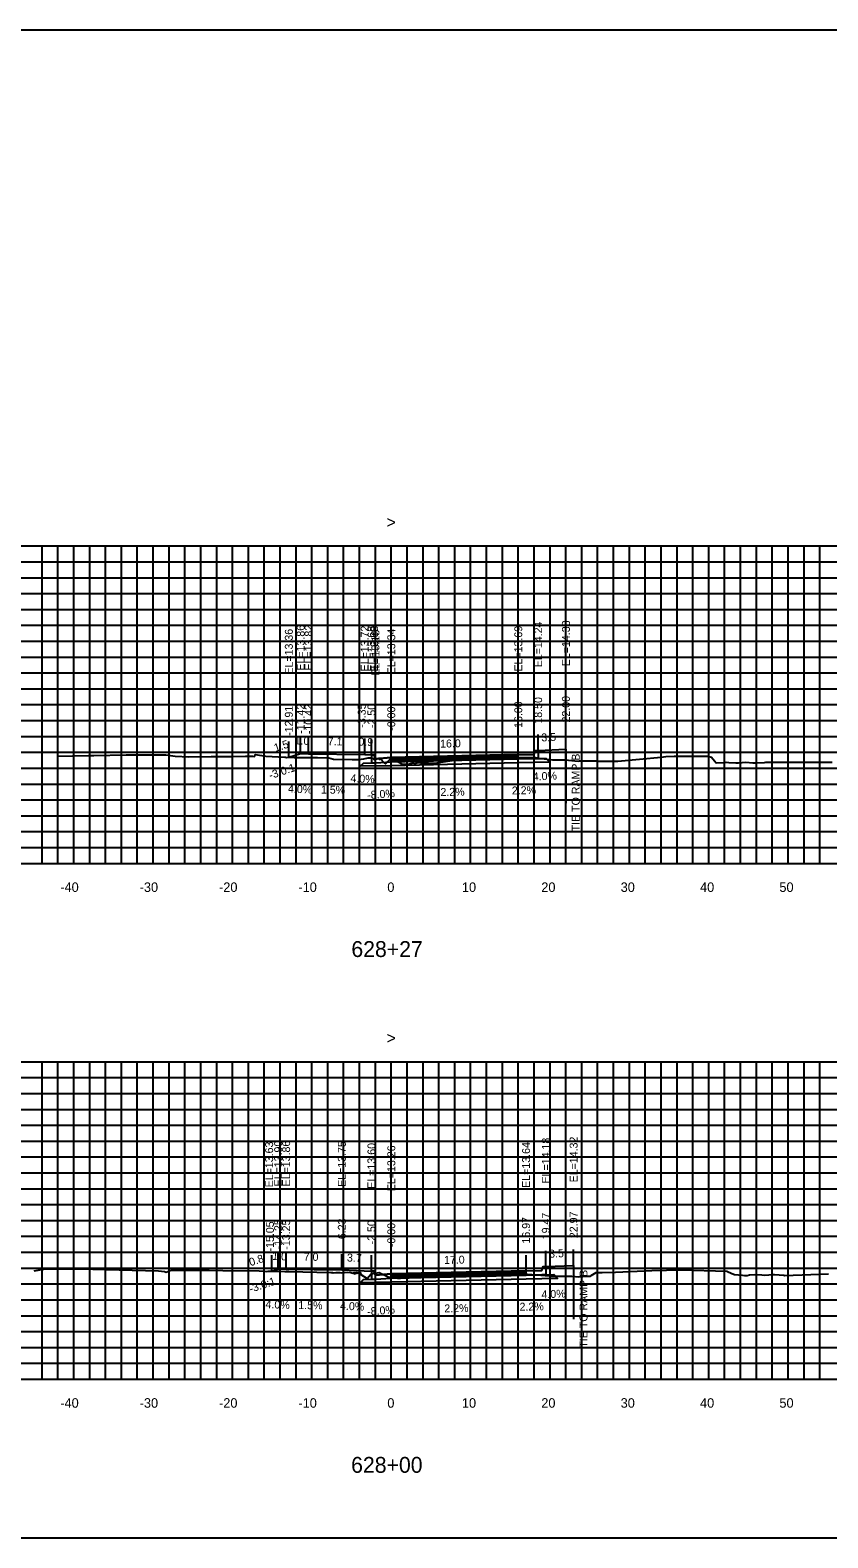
# Model space of a CAD drawing. Extents: x 1797645 to 1803805, y 248417 to 250269.
# Drawn here: x 1802585.5 to 1802686, y 250079.4 to 250269.4 of the extents above; entities that cross this region are included whole.
import ezdxf

# ---------------------------------------------------------------- set-up
doc = ezdxf.new("R2010")
doc.units = 0
for name, color, linetype in [('1', 7, 'Continuous'), ('10', 7, 'Continuous'), ('3', 7, 'Continuous'), ('4', 7, 'Continuous'), ('60', 7, 'Continuous'), ('BASE', 7, 'Continuous'), ('CL-CNST', 7, 'Continuous'), ('Level 62', 7, 'Continuous'), ('LOWER BINDER', 7, 'Continuous'), ('M-ROADS', 7, 'Continuous'), ('UPPER BINDER', 7, 'Continuous'), ('WEARING', 7, 'Continuous')]:
    doc.layers.add(name, color=color, linetype=linetype)

msp = doc.modelspace()

# ---------------------------------------------------------------- linework, layer by layer
for p, q in [((1802649.5, 250178.67), (1802649.5, 250180.67)), ((1802653, 250178.81), (1802653, 250180.81)), ((1802618.09, 250177.8), (1802618.09, 250179.8)), ((1802619.58, 250178.29), (1802619.58, 250180.29)), ((1802620.58, 250178.25), (1802620.58, 250180.25)), ((1802627.65, 250178.15), (1802627.65, 250180.15)), ((1802628.5, 250178.11), (1802628.5, 250180.11)), ((1802631, 250177.77), (1802631, 250179.77)), ((1802647, 250178.13), (1802647, 250180.13)), ((1802615.95, 250113.06), (1802615.95, 250115.06)), ((1802616.75, 250113.33), (1802616.75, 250115.33)), ((1802617.75, 250113.29), (1802617.75, 250115.29)), ((1802624.77, 250113.19), (1802624.77, 250115.19)), ((1802628.5, 250113.04), (1802628.5, 250115.04)), ((1802631, 250112.7), (1802631, 250114.7)), ((1802647.98, 250113.07), (1802647.98, 250115.07)), ((1802650.47, 250113.61), (1802650.47, 250115.61)), ((1802653.97, 250113.75), (1802653.97, 250115.75))]:
    msp.add_line(p, q)
for points in [[(1802481, 250079.43), (1802781, 250079.43), (1802781, 250269.43), (1802481, 250269.43)], [(1802631, 250177.77), (1802629, 250177.61), (1802628.83, 250178.11), (1802628.5, 250178.11), (1802628.5, 250177.08), (1802629, 250177.08), (1802631, 250177.24)], [(1802647, 250178.13), (1802649, 250178.17), (1802649.17, 250178.67), (1802649.5, 250178.67), (1802649.5, 250177.64), (1802649, 250177.64), (1802647, 250177.6)], [(1802631, 250112.7), (1802629, 250112.54), (1802628.83, 250113.04), (1802628.5, 250113.04), (1802628.5, 250112.01), (1802629, 250112.01), (1802631, 250112.17)], [(1802647.98, 250113.07), (1802649.98, 250113.11), (1802650.14, 250113.61), (1802650.47, 250113.61), (1802650.47, 250112.58), (1802649.98, 250112.58), (1802647.98, 250112.54)]]:
    msp.add_lwpolyline(points, close=True)
at = {"layer": '3'}
for p, q in [((1802653, 250178.81), (1802653, 250172.02)), ((1802653.97, 250113.75), (1802653.97, 250106.97))]:
    msp.add_line(p, q, dxfattribs=at)
at = {"layer": '60'}
for p, q in [((1802481, 250164.43), (1802781, 250164.43)), ((1802591, 250164.37), (1802591, 250164.43)), ((1802601, 250164.37), (1802601, 250164.43)), ((1802611, 250164.37), (1802611, 250164.43)), ((1802621, 250164.37), (1802621, 250164.43)), ((1802631, 250164.37), (1802631, 250164.43)), ((1802641, 250164.37), (1802641, 250164.43)), ((1802651, 250164.37), (1802651, 250164.43)), ((1802661, 250164.37), (1802661, 250164.43)), ((1802671, 250164.37), (1802671, 250164.43)), ((1802681, 250164.37), (1802681, 250164.43)), ((1802481, 250099.43), (1802781, 250099.43)), ((1802591, 250099.37), (1802591, 250099.43)), ((1802601, 250099.37), (1802601, 250099.43)), ((1802611, 250099.37), (1802611, 250099.43)), ((1802621, 250099.37), (1802621, 250099.43)), ((1802631, 250099.37), (1802631, 250099.43)), ((1802641, 250099.37), (1802641, 250099.43)), ((1802651, 250099.37), (1802651, 250099.43)), ((1802661, 250099.37), (1802661, 250099.43)), ((1802671, 250099.37), (1802671, 250099.43)), ((1802681, 250099.37), (1802681, 250099.43))]:
    msp.add_line(p, q, dxfattribs=at)
at = {"layer": 'BASE'}
for points in [[(1802631, 250177.24), (1802647, 250177.6), (1802649, 250177.64), (1802649.5, 250177.64), (1802650.5, 250177.66), (1802650.98, 250177.18), (1802647, 250177.1), (1802631, 250176.74), (1802627.09, 250176.66), (1802627.5, 250177.06), (1802628.5, 250177.08), (1802629, 250177.08)], [(1802631, 250112.17), (1802647.98, 250112.54), (1802649.98, 250112.58), (1802650.47, 250112.58), (1802651.47, 250112.61), (1802651.95, 250112.13), (1802647.98, 250112.04), (1802631, 250111.67), (1802627.09, 250111.58), (1802627.5, 250111.98), (1802628.5, 250112.01), (1802629, 250112.01)]]:
    msp.add_lwpolyline(points, close=True, dxfattribs=at)
at = {"layer": 'CL-CNST'}
for points in [[(1802618.09, 250177.8), (1802619.58, 250178.29), (1802620.58, 250178.25), (1802627.65, 250178.15), (1802628.5, 250178.11), (1802628.83, 250178.11), (1802629, 250177.61), (1802631, 250177.77), (1802647, 250178.13), (1802649, 250178.17), (1802649.17, 250178.67), (1802649.5, 250178.67), (1802653, 250178.81)], [(1802615.95, 250113.06), (1802616.75, 250113.33), (1802617.75, 250113.29), (1802624.77, 250113.19), (1802628.5, 250113.04), (1802628.83, 250113.04), (1802629, 250112.54), (1802631, 250112.7), (1802647.98, 250113.07), (1802649.98, 250113.11), (1802650.14, 250113.61), (1802650.47, 250113.61), (1802653.97, 250113.75)]]:
    msp.add_lwpolyline(points, dxfattribs=at)
at = {"layer": 'Level 62'}
for p, q in [((1802481, 250204.43), (1802781, 250204.43)), ((1802587, 250164.43), (1802587, 250204.43)), ((1802589, 250164.43), (1802589, 250204.43)), ((1802591, 250164.43), (1802591, 250204.43)), ((1802593, 250164.43), (1802593, 250204.43)), ((1802595, 250164.43), (1802595, 250204.43)), ((1802597, 250164.43), (1802597, 250204.43)), ((1802599, 250164.43), (1802599, 250204.43)), ((1802601, 250164.43), (1802601, 250204.43)), ((1802603, 250164.43), (1802603, 250204.43)), ((1802605, 250164.43), (1802605, 250204.43)), ((1802607, 250164.43), (1802607, 250204.43)), ((1802609, 250164.43), (1802609, 250204.43)), ((1802611, 250164.43), (1802611, 250204.43)), ((1802613, 250164.43), (1802613, 250204.43)), ((1802615, 250164.43), (1802615, 250204.43)), ((1802617, 250164.43), (1802617, 250204.43)), ((1802619, 250164.43), (1802619, 250204.43)), ((1802621, 250164.43), (1802621, 250204.43)), ((1802623, 250164.43), (1802623, 250204.43)), ((1802625, 250164.43), (1802625, 250204.43)), ((1802627, 250164.43), (1802627, 250204.43)), ((1802629, 250164.43), (1802629, 250204.43)), ((1802631, 250164.43), (1802631, 250204.43)), ((1802633, 250164.43), (1802633, 250204.43)), ((1802635, 250164.43), (1802635, 250204.43)), ((1802637, 250164.43), (1802637, 250204.43)), ((1802639, 250164.43), (1802639, 250204.43)), ((1802641, 250164.43), (1802641, 250204.43)), ((1802643, 250164.43), (1802643, 250204.43)), ((1802645, 250164.43), (1802645, 250204.43)), ((1802647, 250164.43), (1802647, 250204.43)), ((1802649, 250164.43), (1802649, 250204.43)), ((1802651, 250164.43), (1802651, 250204.43)), ((1802653, 250164.43), (1802653, 250204.43)), ((1802655, 250164.43), (1802655, 250204.43)), ((1802657, 250164.43), (1802657, 250204.43)), ((1802659, 250164.43), (1802659, 250204.43)), ((1802661, 250164.43), (1802661, 250204.43)), ((1802663, 250164.43), (1802663, 250204.43)), ((1802665, 250164.43), (1802665, 250204.43)), ((1802667, 250164.43), (1802667, 250204.43)), ((1802669, 250164.43), (1802669, 250204.43)), ((1802671, 250164.43), (1802671, 250204.43)), ((1802673, 250164.43), (1802673, 250204.43)), ((1802675, 250164.43), (1802675, 250204.43)), ((1802677, 250164.43), (1802677, 250204.43)), ((1802679, 250164.43), (1802679, 250204.43)), ((1802681, 250164.43), (1802681, 250204.43)), ((1802683, 250164.43), (1802683, 250204.43)), ((1802685, 250164.43), (1802685, 250204.43)), ((1802481, 250202.43), (1802781, 250202.43)), ((1802481, 250200.43), (1802781, 250200.43)), ((1802481, 250198.43), (1802781, 250198.43)), ((1802481, 250196.43), (1802781, 250196.43)), ((1802481, 250194.43), (1802781, 250194.43)), ((1802481, 250192.43), (1802781, 250192.43)), ((1802481, 250190.43), (1802781, 250190.43)), ((1802481, 250188.43), (1802781, 250188.43)), ((1802481, 250186.43), (1802781, 250186.43)), ((1802481, 250184.43), (1802781, 250184.43)), ((1802481, 250182.43), (1802781, 250182.43)), ((1802481, 250180.43), (1802781, 250180.43)), ((1802481, 250178.43), (1802781, 250178.43)), ((1802481, 250176.43), (1802781, 250176.43)), ((1802481, 250174.43), (1802781, 250174.43)), ((1802481, 250172.43), (1802781, 250172.43)), ((1802481, 250170.43), (1802781, 250170.43)), ((1802481, 250168.43), (1802781, 250168.43)), ((1802481, 250166.43), (1802781, 250166.43)), ((1802481, 250164.43), (1802781, 250164.43)), ((1802481, 250139.43), (1802781, 250139.43)), ((1802587, 250099.43), (1802587, 250139.43)), ((1802589, 250099.43), (1802589, 250139.43)), ((1802591, 250099.43), (1802591, 250139.43)), ((1802593, 250099.43), (1802593, 250139.43)), ((1802595, 250099.43), (1802595, 250139.43)), ((1802597, 250099.43), (1802597, 250139.43)), ((1802599, 250099.43), (1802599, 250139.43)), ((1802601, 250099.43), (1802601, 250139.43)), ((1802603, 250099.43), (1802603, 250139.43)), ((1802605, 250099.43), (1802605, 250139.43)), ((1802607, 250099.43), (1802607, 250139.43)), ((1802609, 250099.43), (1802609, 250139.43)), ((1802611, 250099.43), (1802611, 250139.43)), ((1802613, 250099.43), (1802613, 250139.43)), ((1802615, 250099.43), (1802615, 250139.43)), ((1802617, 250099.43), (1802617, 250139.43)), ((1802619, 250099.43), (1802619, 250139.43)), ((1802621, 250099.43), (1802621, 250139.43)), ((1802623, 250099.43), (1802623, 250139.43)), ((1802625, 250099.43), (1802625, 250139.43)), ((1802627, 250099.43), (1802627, 250139.43)), ((1802629, 250099.43), (1802629, 250139.43)), ((1802631, 250099.43), (1802631, 250139.43)), ((1802633, 250099.43), (1802633, 250139.43)), ((1802635, 250099.43), (1802635, 250139.43)), ((1802637, 250099.43), (1802637, 250139.43)), ((1802639, 250099.43), (1802639, 250139.43)), ((1802641, 250099.43), (1802641, 250139.43)), ((1802643, 250099.43), (1802643, 250139.43)), ((1802645, 250099.43), (1802645, 250139.43)), ((1802647, 250099.43), (1802647, 250139.43)), ((1802649, 250099.43), (1802649, 250139.43)), ((1802651, 250099.43), (1802651, 250139.43)), ((1802653, 250099.43), (1802653, 250139.43)), ((1802655, 250099.43), (1802655, 250139.43)), ((1802657, 250099.43), (1802657, 250139.43)), ((1802659, 250099.43), (1802659, 250139.43)), ((1802661, 250099.43), (1802661, 250139.43)), ((1802663, 250099.43), (1802663, 250139.43)), ((1802665, 250099.43), (1802665, 250139.43)), ((1802667, 250099.43), (1802667, 250139.43)), ((1802669, 250099.43), (1802669, 250139.43)), ((1802671, 250099.43), (1802671, 250139.43)), ((1802673, 250099.43), (1802673, 250139.43)), ((1802675, 250099.43), (1802675, 250139.43)), ((1802677, 250099.43), (1802677, 250139.43)), ((1802679, 250099.43), (1802679, 250139.43)), ((1802681, 250099.43), (1802681, 250139.43)), ((1802683, 250099.43), (1802683, 250139.43)), ((1802685, 250099.43), (1802685, 250139.43)), ((1802481, 250137.43), (1802781, 250137.43)), ((1802481, 250135.43), (1802781, 250135.43)), ((1802481, 250133.43), (1802781, 250133.43)), ((1802481, 250131.43), (1802781, 250131.43)), ((1802481, 250129.43), (1802781, 250129.43)), ((1802481, 250127.43), (1802781, 250127.43)), ((1802481, 250125.43), (1802781, 250125.43)), ((1802481, 250123.43), (1802781, 250123.43)), ((1802481, 250121.43), (1802781, 250121.43)), ((1802481, 250119.43), (1802781, 250119.43)), ((1802481, 250117.43), (1802781, 250117.43)), ((1802481, 250115.43), (1802781, 250115.43)), ((1802481, 250113.43), (1802781, 250113.43)), ((1802481, 250111.43), (1802781, 250111.43)), ((1802481, 250109.43), (1802781, 250109.43)), ((1802481, 250107.43), (1802781, 250107.43)), ((1802481, 250105.43), (1802781, 250105.43)), ((1802481, 250103.43), (1802781, 250103.43)), ((1802481, 250101.43), (1802781, 250101.43)), ((1802481, 250099.43), (1802781, 250099.43))]:
    msp.add_line(p, q, dxfattribs=at)
at = {"layer": 'LOWER BINDER'}
for points in [[(1802647, 250177.6), (1802647, 250177.6), (1802647, 250177.79), (1802631, 250177.43), (1802631, 250177.24)], [(1802647.98, 250112.54), (1802647.98, 250112.54), (1802647.98, 250112.73), (1802631, 250112.36), (1802631, 250112.17)]]:
    msp.add_lwpolyline(points, close=True, dxfattribs=at)
at = {"layer": 'M-ROADS'}
for points in [[(1802588.88, 250177.92), (1802590.83, 250178), (1802592.87, 250178.01), (1802593.53, 250178.01), (1802597.59, 250178.11), (1802598.78, 250178.12), (1802599.93, 250178.12), (1802601.08, 250178.12), (1802602.31, 250178.11), (1802602.59, 250178.11), (1802603.75, 250177.94), (1802605.49, 250177.85), (1802608.31, 250177.91), (1802611.05, 250177.91), (1802612.62, 250177.94), (1802613.08, 250177.94), (1802613.32, 250177.95), (1802613.5, 250177.96), (1802613.52, 250177.94), (1802613.76, 250177.91), (1802613.91, 250178.16), (1802615.18, 250177.93), (1802617.57, 250177.83), (1802617.67, 250177.81), (1802617.78, 250177.79), (1802618.57, 250177.8), (1802618.61, 250177.8), (1802618.77, 250177.79), (1802620.65, 250177.79), (1802620.7, 250177.79), (1802620.81, 250177.78), (1802621.7, 250177.79), (1802623.15, 250177.71), (1802623.7, 250177.57), (1802626.08, 250177.53), (1802626.76, 250177.53), (1802626.85, 250177.53), (1802626.87, 250177.53), (1802627.56, 250177.59), (1802628.09, 250177.73), (1802628.4, 250177.72), (1802628.47, 250177.71), (1802628.75, 250177.65), (1802628.86, 250177.54), (1802629.05, 250177.55), (1802629.45, 250177.67), (1802629.57, 250177.54), (1802629.6, 250177.66), (1802630.11, 250177.1), (1802630.25, 250176.97), (1802630.99, 250177.7), (1802631, 250177.68), (1802631.07, 250177.68), (1802631.37, 250177.52), (1802632.32, 250176.98), (1802632.67, 250176.95), (1802633.28, 250176.99), (1802633.72, 250177.1), (1802633.99, 250177.03), (1802634.3, 250177.13), (1802634.67, 250177.1), (1802634.83, 250177.11), (1802635.7, 250177.1), (1802636.56, 250177.06), (1802636.94, 250177.13), (1802638.95, 250177.45), (1802640.09, 250177.61), (1802642.94, 250177.86), (1802643.87, 250177.83), (1802645.88, 250177.82), (1802645.93, 250177.81), (1802646.05, 250177.81), (1802646.07, 250177.81), (1802646.13, 250177.81), (1802646.62, 250177.79), (1802646.82, 250177.77), (1802647.96, 250177.79), (1802648.94, 250177.81), (1802649.53, 250177.68), (1802651.3, 250177.49), (1802652.95, 250177.49), (1802654.11, 250177.36), (1802654.53, 250177.32), (1802654.72, 250177.36), (1802655.54, 250177.34), (1802656.64, 250177.34), (1802656.85, 250177.34), (1802657.11, 250177.32), (1802657.42, 250177.3), (1802659.12, 250177.32), (1802659.53, 250177.32), (1802664.99, 250177.82), (1802665.61, 250177.89), (1802666.63, 250177.95), (1802668.73, 250177.95), (1802670.84, 250177.95), (1802671.33, 250177.81), (1802671.73, 250177.34), (1802671.95, 250177.09), (1802673.04, 250177.16), (1802673.19, 250177.17), (1802673.53, 250177.14), (1802674.42, 250177.09), (1802674.75, 250177.11), (1802675.65, 250177.17), (1802676.57, 250177.11), (1802676.77, 250177.11), (1802676.95, 250177.09), (1802678.03, 250177.16), (1802678.19, 250177.17), (1802680.44, 250177.18), (1802686.56, 250177.19)], [(1802586, 250113.1), (1802587.49, 250113.32), (1802588.64, 250113.35), (1802589.98, 250113.35), (1802591.53, 250113.35), (1802592.31, 250113.33), (1802593.41, 250113.31), (1802601.65, 250113.09), (1802602.43, 250113.01), (1802602.62, 250112.93), (1802603.27, 250113.15), (1802604.62, 250113.17), (1802608.05, 250113.16), (1802609.79, 250113.12), (1802614.35, 250113.07), (1802615.31, 250113.01), (1802615.48, 250113.05), (1802615.97, 250113.06), (1802617.1, 250113.06), (1802617.57, 250113), (1802617.88, 250113), (1802618.08, 250113), (1802623.38, 250112.89), (1802623.4, 250112.89), (1802623.61, 250112.85), (1802623.69, 250112.84), (1802624, 250112.86), (1802624.51, 250112.86), (1802624.72, 250112.82), (1802625.48, 250112.9), (1802625.88, 250112.89), (1802625.9, 250112.89), (1802626.16, 250112.79), (1802626.33, 250112.85), (1802626.34, 250112.74), (1802626.41, 250112.71), (1802626.54, 250112.85), (1802626.6, 250112.87), (1802626.62, 250112.86), (1802626.65, 250112.73), (1802626.68, 250112.79), (1802626.98, 250112.86), (1802627.02, 250112.86), (1802627.03, 250112.84), (1802627.06, 250112.85), (1802627.17, 250112.62), (1802627.97, 250112.13), (1802628.46, 250112.71), (1802629.46, 250112.86), (1802629.46, 250112.86), (1802629.48, 250112.86), (1802630.7, 250112.27), (1802630.92, 250112.31), (1802631.38, 250112.27), (1802631.83, 250112.17), (1802632.18, 250112.15), (1802633.25, 250112.18), (1802633.68, 250112.26), (1802638.59, 250112.68), (1802640.63, 250112.86), (1802640.96, 250112.86), (1802642.72, 250112.86), (1802643.01, 250112.86), (1802643.37, 250112.85), (1802643.49, 250112.85), (1802643.97, 250112.85), (1802645.59, 250112.86), (1802648.17, 250112.65), (1802650.92, 250112.45), (1802651.14, 250112.42), (1802652.97, 250112.42), (1802653.24, 250112.42), (1802653.3, 250112.42), (1802653.74, 250112.41), (1802654.65, 250112.34), (1802655.63, 250112.41), (1802656.1, 250112.41), (1802656.17, 250112.48), (1802656.82, 250112.89), (1802657.57, 250112.89), (1802659.24, 250112.9), (1802663.84, 250113.11), (1802667.52, 250113.19), (1802673.29, 250113.04), (1802673.91, 250112.76), (1802674.26, 250112.6), (1802675.26, 250112.52), (1802675.51, 250112.51), (1802675.85, 250112.51), (1802676.15, 250112.58), (1802676.82, 250112.63), (1802677.67, 250112.56), (1802678.05, 250112.52), (1802679.06, 250112.6), (1802679.29, 250112.61), (1802680.45, 250112.52), (1802680.54, 250112.51), (1802686.08, 250112.69)]]:
    msp.add_lwpolyline(points, dxfattribs=at)
at = {"layer": 'UPPER BINDER'}
for points in [[(1802647, 250177.79), (1802647, 250177.98), (1802631, 250177.62), (1802631, 250177.43)], [(1802647.98, 250112.73), (1802647.98, 250112.92), (1802631, 250112.55), (1802631, 250112.36)]]:
    msp.add_lwpolyline(points, close=True, dxfattribs=at)
at = {"layer": 'WEARING'}
for points in [[(1802647, 250177.98), (1802647, 250178.13), (1802631, 250177.77), (1802631, 250177.62)], [(1802647.98, 250112.92), (1802647.98, 250113.07), (1802631, 250112.7), (1802631, 250112.55)]]:
    msp.add_lwpolyline(points, close=True, dxfattribs=at)

# ---------------------------------------------------------------- texts
for p in [(1802615.76, 250175.02), (1802613.28, 250110.3)]:
    msp.add_text('-3.0:1', height=1, rotation=18.4349).set_placement(p)
at = {"layer": '1'}
for s, p in [('628+27', (1802625.97, 250152.63)), ('628+00', (1802625.94, 250087.63))]:
    msp.add_text(s, height=2, dxfattribs=at).set_placement(p)
at = {"layer": '10'}
for s, p in [('-40', (1802589.3, 250160.83)), ('-30', (1802599.3, 250160.83)), ('-20', (1802609.3, 250160.83)), ('-10', (1802619.3, 250160.83)), ('0', (1802630.5, 250160.83)), ('10', (1802639.9, 250160.83)), ('20', (1802649.9, 250160.83)), ('30', (1802659.9, 250160.83)), ('40', (1802669.9, 250160.83)), ('50', (1802679.9, 250160.83)), ('-40', (1802589.3, 250095.83)), ('-30', (1802599.3, 250095.83)), ('-20', (1802609.3, 250095.83)), ('-10', (1802619.3, 250095.83)), ('0', (1802630.5, 250095.83)), ('10', (1802639.9, 250095.83)), ('20', (1802649.9, 250095.83)), ('30', (1802659.9, 250095.83)), ('40', (1802669.9, 250095.83)), ('50', (1802679.9, 250095.83))]:
    msp.add_text(s, height=1.2, dxfattribs=at).set_placement(p)
at = {"layer": '3'}
for s, p in [('EL=13.36', (1802618.59, 250188.22)), ('EL=13.86', (1802620.08, 250188.72)), ('EL=13.82', (1802621.08, 250188.73)), ('EL=13.72', (1802628.15, 250188.62)), ('EL=13.68', (1802629, 250188.59)), ('EL=13.68', (1802629.33, 250188.59)), ('EL=13.34', (1802631.5, 250188.25)), ('EL=13.69', (1802647.5, 250188.6)), ('EL=14.24', (1802650, 250189.14)), ('EL=14.38', (1802653.5, 250189.28)), ('EL=13.18', (1802629.5, 250188.09)), ('-11.42', (1802620.08, 250180.75)), ('-10.42', (1802621.08, 250180.71)), ('-3.35', (1802627.78, 250181.53)), ('-2.50', (1802629, 250181.48)), ('16.00', (1802647.5, 250181.5)), ('18.50', (1802650, 250182.04)), ('22.00', (1802653.5, 250182.18)), ('-12.91', (1802618.59, 250180.5)), ('-0.00', (1802631.5, 250181.14)), ('TIE TO RAMP B', (1802654.74, 250168.46)), ('EL=13.63', (1802616.11, 250123.6)), ('EL=13.90', (1802617.25, 250123.72)), ('EL=13.86', (1802618.25, 250123.72)), ('EL=13.75', (1802625.27, 250123.66)), ('EL=14.18', (1802650.97, 250124.09)), ('EL=14.32', (1802654.47, 250124.23)), ('EL=13.60', (1802629, 250123.43)), ('EL=13.26', (1802631.5, 250123.12)), ('EL=13.64', (1802648.48, 250123.54)), ('19.47', (1802650.97, 250117.06)), ('22.97', (1802654.47, 250117.2)), ('-15.05', (1802616.21, 250115.52)), ('-14.25', (1802617.25, 250115.79)), ('-13.25', (1802618.25, 250115.75)), ('-6.23', (1802625.27, 250116.63)), ('-2.50', (1802629, 250116.41)), ('-0.00', (1802631.5, 250116.07)), ('16.97', (1802648.48, 250116.52)), ('TIE TO RAMP B', (1802655.72, 250103.4))]:
    msp.add_text(s, height=1, rotation=90, dxfattribs=at).set_placement(p)
at = {"layer": '4'}
for s, rotation, p in [('3.5', 2.2906, (1802649.92, 250179.79)), ('1.5', 18.4349, (1802616.41, 250178.47)), ('1.0', 357.7094, (1802618.81, 250179.43)), ('7.1', 359.1406, (1802622.98, 250179.32)), ('0.9', 357.7094, (1802626.84, 250179.28)), ('16.0', 1.2603, (1802637.16, 250179.01)), ('4.0%', 357.7094, (1802625.84, 250174.66)), ('4.0%', 2.2906, (1802648.84, 250174.87)), ('4.0%', 357.7094, (1802617.97, 250173.35)), ('1.5%', 359.1406, (1802622.13, 250173.23)), ('-8.0%', 4.5739, (1802628, 250172.52)), ('2.2%', 1.2603, (1802637.2, 250172.91)), ('2.2%', 1.2603, (1802646.2, 250173.11)), ('0.8', 18.4349, (1802613.27, 250113.65)), ('1.0', 357.7094, (1802615.98, 250114.46)), ('7.0', 359.1406, (1802619.96, 250114.36)), ('3.7', 357.7094, (1802625.4, 250114.26)), ('17.0', 1.2603, (1802637.65, 250113.94)), ('3.5', 2.2906, (1802650.9, 250114.73)), ('4.0%', 2.2906, (1802649.94, 250109.61)), ('4.0%', 357.7094, (1802615.14, 250108.39)), ('1.5%', 359.1406, (1802619.28, 250108.27)), ('4.0%', 357.7094, (1802624.53, 250108.19)), ('-8.0%', 4.5739, (1802628, 250107.44)), ('2.2%', 1.2603, (1802637.69, 250107.84)), ('2.2%', 1.2603, (1802647.17, 250108.05))]:
    msp.add_text(s, height=1, rotation=rotation, dxfattribs=at).set_placement(p)
at = {"layer": '60'}
for p in [(1802630.39, 250206.68), (1802630.39, 250141.68)]:
    msp.add_text('>', height=1.5, dxfattribs=at).set_placement(p)

doc.saveas('drawing.dxf')
